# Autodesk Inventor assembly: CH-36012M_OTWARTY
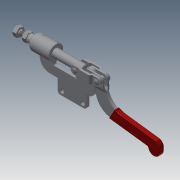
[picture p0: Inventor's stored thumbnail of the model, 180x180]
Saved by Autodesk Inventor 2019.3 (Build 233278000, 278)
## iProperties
Company: Î¢ÈíÖÐ¹ú
Created: 2012-09
Part Number: CH-36012M_OTWARTY
Material: Ogólny
Description: STEP AP203
Document SubType Name: Assembly
Designer: CADENGINEERING4
Sending System: SolidWorks 2010
Preprocessor: SwSTEP 2.0
Title: CH-36012M.STEP
Author: Î¢ÈíÓÃ»§
Revision Number: ÈÎºÎ
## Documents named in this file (13)
- D:\Vault_2016\Projekty\STRONA\Push-pull clamp\CH-36012M\CH-36012M_OTWARTY.iam
- D:\Vault_2016\Projekty\STRONA\Push-pull clamp\CH-36012M\CH-36010M-04 CONNECTING-PLATE.ipt
- D:\Vault_2016\Projekty\STRONA\Push-pull clamp\CH-36012M\CH-36010M-11.ipt
- D:\Vault_2016\Projekty\STRONA\Push-pull clamp\CH-36012M\CH-36010M-08.ipt
- D:\Vault_2016\Projekty\STRONA\Push-pull clamp\CH-36012M\CH-36012M-01 BASE.ipt
- D:\Vault_2016\Projekty\STRONA\Push-pull clamp\CH-36012M\CH-36010M-03 HANDLE.ipt
- D:\Vault_2016\Projekty\STRONA\Push-pull clamp\CH-36012M\CH-36010M-02 CREST STALK.ipt
- D:\Vault_2016\Projekty\STRONA\Push-pull clamp\CH-36012M\CH-36010M-05 LEAD SET.ipt
- D:\Vault_2016\Projekty\STRONA\Push-pull clamp\CH-36012M\CH-SA-105015 SPINDLE SUPPLIED.ipt
- D:\Vault_2016\Projekty\STRONA\Push-pull clamp\CH-36012M\CH-36010M-10.ipt
- D:\Vault_2016\Projekty\STRONA\Push-pull clamp\CH-36012M\M10 Nut.ipt
- D:\Vault_2016\Projekty\STRONA\Push-pull clamp\CH-36012M\CH-36010M-09.ipt
- D:\Vault_2016\Projekty\STRONA\Push-pull clamp\CH-36012M\CH-36010M-07.ipt
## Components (13 placed, 13 different names)
1. CH-36010M-04 CONNECTING-PLATE_1 — Zestawiające:10, Zestawiające:11, Zestawiające:12, Zestawiające:13, Zestawiające:14, Zestawiające:21, Zestawiające:22
2. CH-36010M-11_2 — Zestawiające:18, Zestawiające:21
3. CH-36010M-08_3 — Zestawiające:8, Równoległe:2, Zestawiające:13, Zestawiające:19
4. CH-36012M-01 BASE_4 — Zestawiające:5, Równoległe:1, Zestawiające:6, Zestawiające:15, Zestawiające:16
5. CH-36010M-03 HANDLE_5 — Zestawiające:6, Zestawiające:7, Zestawiające:8, Równoległe:2, Zestawiające:9, Zestawiające:10, Zestawiające:23
6. CH-36010M-02 CREST STALK_6 — Zestawiające:3, Zestawiające:4, Zestawiające:14, Zestawiające:17, Zestawiające:18
7. CH-36010M-05 LEAD SET_7 — Zestawiające:15, Zestawiające:16, Zestawiające:17
8. CH-SA-105015 SPINDLE SUPPLIED_8 — Zestawiające:1, Zestawiające:2, Zestawiające:4
9. CH-36010M-10_9 — Zestawiające:19, Zestawiające:22
10. M10 Nut_10 — Zestawiające:1, Zestawiające:2, Zestawiające:3
11. CH-36010M-09_11 — Zestawiające:20, Zestawiające:23
12. CH-36010M-07_12 — Zestawiające:5, Równoległe:1, Zestawiające:7, Zestawiające:20
13. CH-36010M-04 CONNECTING-PLATE_13 — Zestawiające:9, Zestawiające:11, Zestawiające:12
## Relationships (25: Mate 23, Flush 2)
- Zestawiające:1 [Mate]: CH-SA-105015 SPINDLE SUPPLIED_8 ↔ M10 Nut_10
- Zestawiające:2 [Mate]: CH-SA-105015 SPINDLE SUPPLIED_8 ↔ M10 Nut_10
- Zestawiające:3 [Mate]: CH-36010M-02 CREST STALK_6 ↔ M10 Nut_10
- Zestawiające:4 [Mate]: CH-36010M-02 CREST STALK_6 ↔ CH-SA-105015 SPINDLE SUPPLIED_8
- Zestawiające:5 [Mate]: CH-36012M-01 BASE_4 ↔ CH-36010M-07_12
- Równoległe:1 [Flush]: CH-36012M-01 BASE_4 ↔ CH-36010M-07_12
- Zestawiające:6 [Mate]: CH-36012M-01 BASE_4 ↔ CH-36010M-03 HANDLE_5
- Zestawiające:7 [Mate]: CH-36010M-03 HANDLE_5 ↔ CH-36010M-07_12
- Zestawiające:8 [Mate]: CH-36010M-08_3 ↔ CH-36010M-03 HANDLE_5
- Równoległe:2 [Flush]: CH-36010M-08_3 ↔ CH-36010M-03 HANDLE_5
- Zestawiające:9 [Mate]: CH-36010M-03 HANDLE_5 ↔ CH-36010M-04 CONNECTING-PLATE_13
- Zestawiające:10 [Mate]: CH-36010M-04 CONNECTING-PLATE_1 ↔ CH-36010M-03 HANDLE_5
- Zestawiające:11 [Mate]: CH-36010M-04 CONNECTING-PLATE_1 ↔ CH-36010M-04 CONNECTING-PLATE_13
- Zestawiające:12 [Mate]: CH-36010M-04 CONNECTING-PLATE_1 ↔ CH-36010M-04 CONNECTING-PLATE_13
- Zestawiające:13 [Mate]: CH-36010M-04 CONNECTING-PLATE_1 ↔ CH-36010M-08_3
- Zestawiające:14 [Mate]: CH-36010M-04 CONNECTING-PLATE_1 ↔ CH-36010M-02 CREST STALK_6
- Zestawiające:15 [Mate]: CH-36012M-01 BASE_4 ↔ CH-36010M-05 LEAD SET_7
- Zestawiające:16 [Mate]: CH-36012M-01 BASE_4 ↔ CH-36010M-05 LEAD SET_7
- Zestawiające:17 [Mate]: CH-36010M-02 CREST STALK_6 ↔ CH-36010M-05 LEAD SET_7
- Zestawiające:18 [Mate]: CH-36010M-11_2 ↔ CH-36010M-02 CREST STALK_6
- Zestawiające:19 [Mate]: CH-36010M-08_3 ↔ CH-36010M-10_9
- Zestawiające:20 [Mate]: CH-36010M-09_11 ↔ CH-36010M-07_12
- Zestawiające:21 [Mate]: CH-36010M-04 CONNECTING-PLATE_1 ↔ CH-36010M-11_2
- Zestawiające:22 [Mate]: CH-36010M-04 CONNECTING-PLATE_1 ↔ CH-36010M-10_9
- Zestawiające:23 [Mate]: CH-36010M-03 HANDLE_5 ↔ CH-36010M-09_11
